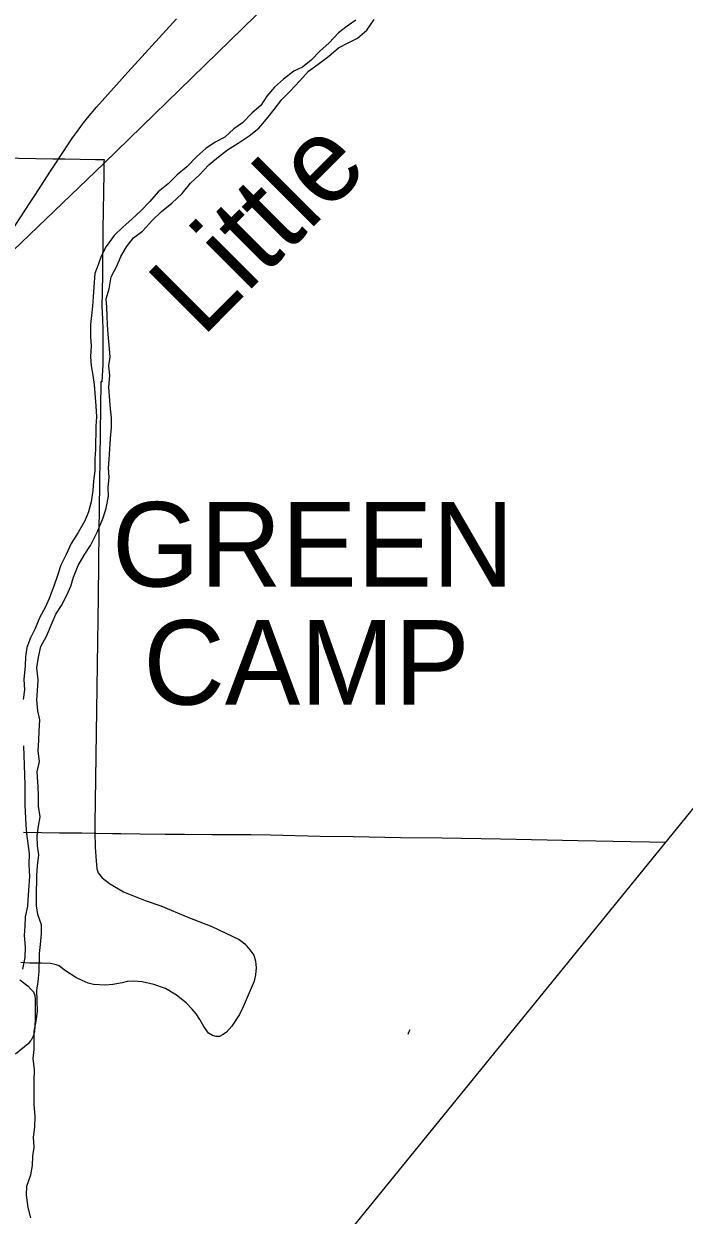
# Model space of a CAD drawing. Extents: x 0 to 680, y 0 to 440.
# Drawn here: x 414.44 to 440.48, y 243.12 to 290.12 of the extents above; entities that cross this region are included whole.
import ezdxf

# ---------------------------------------------------------------- set-up
doc = ezdxf.new("R2010")
doc.units = 0
for name, color, linetype in [('DV_X_Corp_Line', 7, 'Continuous'), ('GM_X_Corporation_Text', 7, 'Continuous'), ('GM_X_County_Road', 7, 'Continuous'), ('GM_X_Major_River', 7, 'Continuous'), ('GM_X_Major_River_Text', 7, 'Continuous'), ('GM_X_State_Route', 7, 'Continuous'), ('RD_X_RR_2', 7, 'Continuous'), ('SC_Shading3', 7, 'Continuous'), ('SH_Text', 7, 'Continuous')]:
    doc.layers.add(name, color=color, linetype=linetype)

msp = doc.modelspace()

# ---------------------------------------------------------------- linework, layer by layer
at = {"layer": 'DV_X_Corp_Line'}
for points in [[(408.821, 284.918), (415.576, 284.794), (415.813, 284.79), (416.049, 284.786), (417.262, 284.763), (417.28, 284.763), (417.602, 284.757), (417.6, 284.664), (417.589, 284.226), (417.559, 281.996), (417.535, 280.217), (417.518, 278.923), (417.527, 278.768), (417.548, 278.09), (417.559, 277.456), (417.549, 276.671), (417.516, 275.987), (417.478, 275.988), (417.411, 270.982), (417.399, 270.124), (417.364, 267.519), (417.244, 258.543), (417.242, 258.409), (417.242, 258.374), (417.239, 258.209), (417.243, 258.044), (417.243, 258.009), (417.246, 257.877), (417.251, 257.636), (417.279, 257.275), (417.321, 256.783), (417.376, 256.624), (417.522, 256.423), (417.813, 256.201), (418.374, 255.876), (419.22, 255.529), (419.837, 255.321), (420.904, 254.871), (421.854, 254.504), (422.935, 253.992), (423.15, 253.825), (423.358, 253.583), (423.504, 253.375), (423.58, 253.146), (423.601, 252.876), (423.573, 252.606), (423.518, 252.349), (423.331, 251.892), (423.095, 251.337), (422.95, 251.032), (422.638, 250.575), (422.43, 250.346), (422.306, 250.242), (422.16, 250.173), (422.021, 250.172), (421.876, 250.214), (421.723, 250.297), (421.536, 250.567), (421.377, 250.838), (421.238, 251.066), (421.079, 251.246), (420.843, 251.496), (420.455, 251.801), (420.025, 252.057), (419.56, 252.216), (419.11, 252.32), (418.77, 252.348), (418.514, 252.334), (418.313, 252.292), (417.946, 252.216), (417.648, 252.188), (417.19, 252.223), (416.975, 252.278), (416.74, 252.375), (416.483, 252.493), (416.268, 252.638), (416.046, 252.791), (415.831, 252.957), (415.707, 252.992), (415.485, 253.054), (415.123, 253.06), (414.78, 253.066), (414.674, 253.068), (414.314, 253.088)], [(414.279, 252.402), (414.605, 252.153), (414.712, 252.038), (414.813, 251.931), (414.875, 251.792), (414.889, 251.647), (414.883, 250.829), (414.876, 250.607), (414.862, 250.358), (414.806, 250.184), (414.723, 250.025), (414.702, 249.997), (414.613, 249.879), (414.112, 249.473)]]:
    msp.add_lwpolyline(points, dxfattribs=at)
at = {"layer": 'GM_X_County_Road'}
for points in [[(414.421, 258.224), (415.846, 258.207), (416.724, 258.201), (417.242, 258.192), (417.277, 258.191)], [(417.277, 258.191), (417.94, 258.178), (418.266, 258.172), (419.029, 258.161), (420.011, 258.154), (420.338, 258.152), (420.775, 258.149), (421.869, 258.14), (423.398, 258.133), (424.164, 258.124), (426.133, 258.076), (427.441, 258.059), (429.3, 258.024), (430.941, 258.002), (433.238, 257.966), (436.299, 257.907), (438.375, 257.858), (439.128, 257.845), (439.733, 257.831)]]:
    msp.add_lwpolyline(points, dxfattribs=at)
at = {"layer": 'GM_X_Major_River'}
for points in [[(415.011, 265.13), (415.112, 265.555), (415.331, 265.965), (415.553, 266.482), (415.705, 266.826), (415.924, 267.169), (416.13, 267.579), (416.296, 267.937), (416.394, 268.282), (416.575, 268.746), (416.821, 269.155), (417.067, 269.538), (417.343, 270.094), (417.564, 270.624), (417.69, 271.009), (417.778, 271.487), (417.77, 271.821), (417.804, 272.234), (417.783, 272.582), (417.802, 272.928), (417.836, 273.355), (417.856, 273.755), (417.89, 274.194), (417.896, 274.568), (417.862, 274.929), (417.827, 275.263), (417.796, 275.784), (417.83, 276.237), (417.797, 276.625), (417.843, 276.984), (417.81, 277.438), (417.764, 277.879), (417.744, 278.24), (417.723, 278.587), (417.715, 278.935), (417.681, 279.269), (417.807, 279.667), (417.881, 280.133), (418.115, 280.582), (418.267, 280.94), (418.487, 281.323), (418.759, 281.679), (419.122, 281.94), (419.502, 282.36), (419.867, 282.714), (420.272, 283.041), (420.677, 283.421), (421.017, 283.829), (421.368, 284.156), (421.734, 284.55), (422.112, 284.864), (422.476, 285.151), (422.892, 285.411), (423.323, 285.697), (423.701, 285.998), (424.013, 286.353), (424.312, 286.735), (424.611, 287.13), (424.949, 287.458), (425.328, 287.865), (425.667, 288.246), (426.044, 288.52), (426.462, 288.846), (426.854, 289.173), (427.256, 289.38), (427.605, 289.547), (427.97, 289.861), (428.256, 290.283)], [(427.537, 290.256), (427.187, 290.021), (426.85, 289.76), (426.484, 289.366), (426.12, 289.039), (425.768, 288.685), (425.43, 288.41), (425.082, 288.243), (424.677, 287.929), (424.326, 287.615), (424.028, 287.26), (423.782, 286.89), (423.444, 286.603), (423.065, 286.209), (422.715, 285.975), (422.364, 285.647), (421.988, 285.453), (421.611, 285.193), (421.26, 284.879), (420.868, 284.472), (420.49, 284.158), (420.125, 283.804), (419.733, 283.49), (419.408, 283.109), (419.056, 282.741), (418.704, 282.414), (418.353, 282.113), (418.002, 281.759), (417.688, 281.337), (417.482, 280.953), (417.37, 280.608), (417.245, 280.264), (417.196, 279.744), (417.176, 279.344), (417.144, 278.984), (417.111, 278.611), (417.065, 278.252), (417.07, 277.758), (417.091, 277.411), (417.071, 276.984), (417.091, 276.623), (417.165, 276.262), (417.212, 275.887), (417.257, 275.379), (417.278, 275.046), (417.298, 274.618), (417.278, 274.245), (417.263, 273.324), (417.244, 272.951), (417.236, 272.484), (417.189, 272.085), (417.156, 271.712), (417.096, 271.259), (416.983, 270.861), (416.844, 270.516), (416.583, 270.053), (416.31, 269.618)], [(416.31, 269.618), (416.103, 269.181), (415.897, 268.758), (415.756, 268.32), (415.617, 267.935), (415.436, 267.444), (415.283, 267.087), (415.064, 266.704), (414.884, 266.266), (414.705, 265.896), (414.552, 265.511), (414.506, 265.139), (414.487, 264.792), (414.438, 264.246), (414.458, 263.845), (414.412, 263.459)], [(414.711, 243.011), (414.612, 243.427), (414.54, 243.908), (414.559, 244.268), (414.713, 244.706), (414.785, 245.078), (414.792, 245.452), (414.851, 245.798), (414.817, 246.199), (414.877, 246.598), (414.884, 247.011), (414.839, 247.506), (414.847, 248), (414.841, 248.427), (414.861, 248.853), (414.802, 249.295), (414.848, 249.654), (414.841, 250.028), (414.846, 250.361), (414.92, 250.774), (414.979, 251.16), (414.96, 251.6), (414.953, 251.987), (414.999, 252.334), (415.045, 252.733), (415.057, 253.44), (415.09, 253.8), (415.137, 254.226), (415.129, 254.573), (414.99, 254.976), (414.942, 255.323), (414.935, 255.697), (414.949, 256.524), (414.981, 256.897), (415.029, 257.337), (414.981, 257.685), (414.961, 258.085), (415.021, 258.471), (415.08, 258.83), (415.021, 259.258), (415.014, 259.672), (415.007, 260.019), (414.963, 260.607), (415.05, 261.019), (415.003, 261.42), (415.024, 261.86), (415.043, 262.207), (415.064, 262.66), (414.99, 263.009), (414.957, 263.449), (414.976, 263.809), (414.997, 264.236), (414.951, 264.717), (415.011, 265.13)], [(414.421, 261.631), (414.441, 261.243), (414.449, 260.896), (414.468, 260.469), (414.476, 260.108), (414.482, 259.708), (414.476, 259.294), (414.516, 258.52), (414.537, 258.173), (414.597, 257.785), (414.644, 257.383), (414.636, 256.957), (414.655, 256.476), (414.636, 256.116), (414.603, 255.756), (414.583, 255.316), (414.496, 254.891), (414.476, 254.517), (414.457, 254.158), (414.489, 253.69), (414.482, 253.29), (414.382, 252.824)]]:
    msp.add_lwpolyline(points, dxfattribs=at)
at = {"layer": 'GM_X_State_Route'}
for points in [[(415.774, 284.739), (415.793, 284.768), (416.362, 285.613), (416.51, 285.831), (416.68, 286.059), (416.81, 286.227), (416.951, 286.404), (417.305, 286.822), (418.545, 288.21), (420.456, 290.316)], [(414.898, 283.389), (415.462, 284.264), (415.774, 284.739)], [(408.086, 271.733), (408.132, 271.791), (408.409, 272.294), (408.762, 272.925), (409.053, 273.444), (409.37, 274.011), (409.428, 274.115), (410.118, 275.348), (410.596, 276.208), (411.286, 277.452), (411.873, 278.503), (412.629, 279.837), (413.081, 280.588), (413.734, 281.601), (414.691, 283.068), (414.898, 283.389)], [(429.658, 250.428), (429.608, 250.326), (429.589, 250.25)]]:
    msp.add_lwpolyline(points, dxfattribs=at)
at = {"layer": 'RD_X_RR_2'}
msp.add_lwpolyline([(365.587, 215.989), (372.377, 226.622), (380.238, 238.84), (389.713, 253.215), (394.045, 260.328), (395.778, 262.864), (396.554, 263.768), (397.211, 264.649), (398.057, 265.641), (400.091, 267.7), (402.496, 269.941), (406.01, 273.466), (412.053, 279.303), (417.596, 284.611), (426.566, 293.352), (435.599, 302.168), (441.572, 308.078), (456.142, 322.286), (463.879, 329.729), (466.921, 332.716)], dxfattribs=at)
at = {"layer": 'SC_Shading3'}
for points in [[(408.821, 284.918), (415.576, 284.794), (415.813, 284.79), (416.049, 284.786), (417.262, 284.763), (417.28, 284.763), (417.602, 284.757), (417.6, 284.664), (417.589, 284.226), (417.559, 281.996), (417.535, 280.217), (417.518, 278.923), (417.527, 278.768), (417.548, 278.09), (417.559, 277.456), (417.549, 276.671), (417.516, 275.987), (417.478, 275.988), (417.411, 270.982), (417.399, 270.124), (417.364, 267.519), (417.244, 258.543), (417.242, 258.409), (417.242, 258.374), (417.239, 258.209), (417.243, 258.044), (417.243, 258.009), (417.246, 257.877), (417.251, 257.636), (417.279, 257.275), (417.321, 256.783), (417.376, 256.624), (417.522, 256.423), (417.813, 256.201), (418.374, 255.876), (419.22, 255.529), (419.837, 255.321), (420.904, 254.871), (421.854, 254.504), (422.935, 253.992), (423.15, 253.825), (423.358, 253.583), (423.504, 253.375), (423.58, 253.146), (423.601, 252.876), (423.573, 252.606), (423.518, 252.349), (423.331, 251.892), (423.095, 251.337), (422.95, 251.032), (422.638, 250.575), (422.43, 250.346), (422.306, 250.242), (422.16, 250.173), (422.021, 250.172), (421.876, 250.214), (421.723, 250.297), (421.536, 250.567), (421.377, 250.838), (421.238, 251.066), (421.079, 251.246), (420.843, 251.496), (420.455, 251.801), (420.025, 252.057), (419.56, 252.216), (419.11, 252.32), (418.77, 252.348), (418.514, 252.334), (418.313, 252.292), (417.946, 252.216), (417.648, 252.188), (417.19, 252.223), (416.975, 252.278), (416.74, 252.375), (416.483, 252.493), (416.268, 252.638), (416.046, 252.791), (415.831, 252.957), (415.707, 252.992), (415.485, 253.054), (415.123, 253.06), (414.78, 253.066), (414.674, 253.068), (414.314, 253.088)], [(414.279, 252.402), (414.605, 252.153), (414.712, 252.038), (414.813, 251.931), (414.875, 251.792), (414.889, 251.647), (414.883, 250.829), (414.876, 250.607), (414.862, 250.358), (414.806, 250.184), (414.723, 250.025), (414.702, 249.997), (414.613, 249.879), (414.112, 249.473)]]:
    msp.add_lwpolyline(points, dxfattribs=at)
at = {"layer": 'SH_Text'}
msp.add_lwpolyline([(30, 430), (466.921, 430), (466.921, 291.274), (342.899, 138.716), (30, 138.716)], close=True, dxfattribs=at)

# ---------------------------------------------------------------- texts
at = {"layer": 'GM_X_Corporation_Text'}
for s, p in [('GREEN', (417.917, 267.918)), ('CAMP', (419.149, 263.26))]:
    msp.add_text(s, height=3.3333, rotation=0, dxfattribs=at).set_placement(p)
at = {"layer": 'GM_X_Major_River_Text'}
msp.add_text('Little', height=3.334, rotation=45.0206, dxfattribs=at).set_placement((421.465, 277.708))

doc.saveas('drawing.dxf')
